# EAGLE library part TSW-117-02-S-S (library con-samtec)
THROUGH-HOLE .025" SQ POST HEADER Source: Samtec TSW.pdf
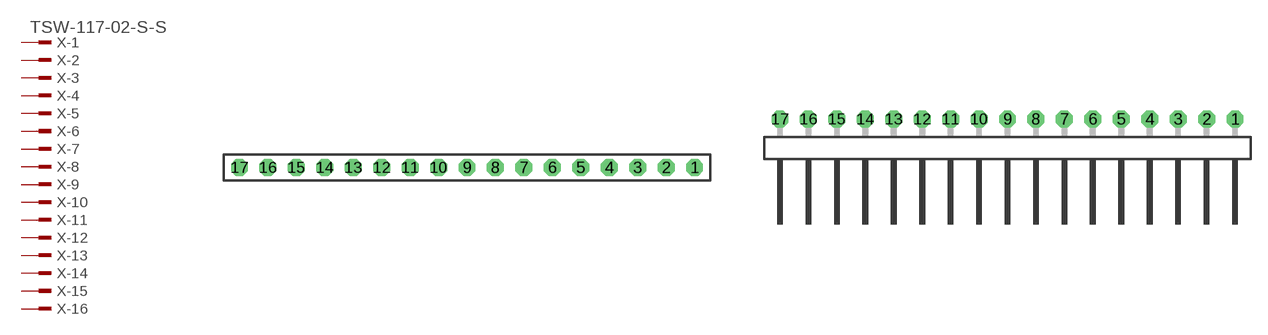
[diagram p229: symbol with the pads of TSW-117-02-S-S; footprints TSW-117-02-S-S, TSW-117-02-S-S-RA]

Designator prefix X; gates -1=MPINV -2=MPIN -3=MPIN -4=MPIN -5=MPIN -6=MPIN -7=MPIN -8=MPIN -9=MPIN -10=MPIN -11=MPIN -12=MPIN -13=MPIN -14=MPIN -15=MPIN -16=MPIN -17=MPIN

## TSW-117-02-S-S (OC_FARNELL: unknown; OC_NEWARK: unknown)  [TSW-117-02-S-S]
1  -1:1  pas
2  -2:1  pas
3  -3:1  pas
4  -4:1  pas
5  -5:1  pas
6  -6:1  pas
7  -7:1  pas
8  -8:1  pas
9  -9:1  pas
10  -10:1  pas
11  -11:1  pas
12  -12:1  pas
13  -13:1  pas
14  -14:1  pas
15  -15:1  pas
16  -16:1  pas
17  -17:1  pas

## TSW-117-02-S-S-RA (OC_FARNELL: unknown; OC_NEWARK: unknown)  [TSW-117-02-S-S-RA]
Pads as for TSW-117-02-S-S

## Footprint TSW-117-02-S-S (pad centres in mm)
THROUGH-HOLE .025" SQ POST HEADER Source: Samtec TSW.pdf
drill 1 pad 1.5 octagon: 1 20.32,0; 2 17.78,0; 3 15.24,0; 4 12.7,0; 5 10.16,0; 6 7.62,0; 7 5.08,0; 8 2.54,0; 9 0,0; 10 -2.54,0; 11 -5.08,0; 12 -7.62,0; 13 -10.16,0; 14 -12.7,0; 15 -15.24,0; 16 -17.78,0; 17 -20.32,0

## Footprint TSW-117-02-S-S-RA (pad centres in mm)
THROUGH-HOLE .025" SQ POST HEADER Source: Samtec TSW.pdf
drill 1 pad 1.5 octagon: 1 20.32,1.524; 2 17.78,1.524; 3 15.24,1.524; 4 12.7,1.524; 5 10.16,1.524; 6 7.62,1.524; 7 5.08,1.524; 8 2.54,1.524; 9 0,1.524; 10 -2.54,1.524; 11 -5.08,1.524; 12 -7.62,1.524; 13 -10.16,1.524; 14 -12.7,1.524; 15 -15.24,1.524; 16 -17.78,1.524; 17 -20.32,1.524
